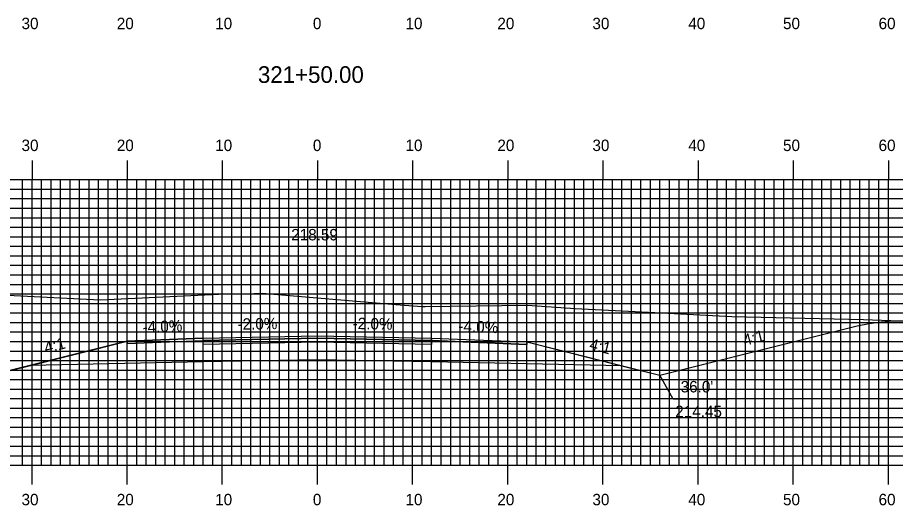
# Model space of a CAD drawing. Extents: x 1820424 to 1820768, y 442591 to 442811.
# Drawn here: x 1820558.7 to 1820650.9, y 442649.4 to 442700.7 of the extents above; entities that cross this region are included whole.
import ezdxf

# ---------------------------------------------------------------- set-up
doc = ezdxf.new("R2010")
doc.units = 0
for name, color, linetype in [('ANNOTATION', 7, 'Continuous'), ('D_Roadway_Centerline', 7, 'Continuous'), ('D_Roadway_Centerline_Text', 7, 'Continuous'), ('D_Roadway_Edge_Shoulder', 7, 'Continuous'), ('D_Roadway_Edge_TW', 7, 'Continuous'), ('D_Roadway_Pavement', 7, 'Continuous'), ('D_Roadway_SlopeLines', 7, 'Continuous'), ('D_Roadway_SubGrade', 7, 'Continuous'), ('H_V ANNOTATION', 7, 'Continuous'), ('MAJOR', 7, 'Continuous'), ('MINOR', 7, 'Continuous'), ('S_Roadway_Centerline', 7, 'Continuous')]:
    doc.layers.add(name, color=color, linetype=linetype)

msp = doc.modelspace()

# ---------------------------------------------------------------- linework, layer by layer
at = {"layer": 'ANNOTATION'}
msp.add_lwpolyline([(1820633.287, 442660.593), (1820627.596, 442660.593), (1820626.204, 442663.112)], dxfattribs=at)
at = {"layer": 'D_Roadway_Centerline'}
msp.add_lwpolyline([(1820513.438, 442673.203), (1820514.688, 442673.15), (1820515.938, 442673.023), (1820517.188, 442672.821), (1820518.438, 442672.546), (1820556.03, 442663.148), (1820560.03, 442664.148), (1820570.204, 442666.692), (1820578.204, 442667.012), (1820590.204, 442667.252), (1820602.204, 442667.012), (1820612.204, 442666.612), (1820622.204, 442664.112), (1820626.204, 442663.112), (1820646.944, 442668.297), (1820648.194, 442668.564), (1820649.444, 442668.742), (1820650.694, 442668.83), (1820651.944, 442668.828)], dxfattribs=at)
at = {"layer": 'D_Roadway_Edge_Shoulder'}
for points in [[(1820578.204, 442667.012), (1820570.204, 442666.692), (1820570.204, 442666.442), (1820578.204, 442666.762)], [(1820602.204, 442667.012), (1820612.204, 442666.612), (1820612.204, 442666.362), (1820602.204, 442666.762)]]:
    msp.add_lwpolyline(points, close=True, dxfattribs=at)
at = {"layer": 'D_Roadway_Edge_TW'}
msp.add_lwpolyline([(1820578.204, 442666.762), (1820578.204, 442667.012), (1820590.204, 442667.252), (1820602.204, 442667.012), (1820602.204, 442666.762), (1820590.204, 442667.002)], close=True, dxfattribs=at)
at = {"layer": 'D_Roadway_Pavement'}
msp.add_lwpolyline([(1820578.204, 442666.345), (1820578.204, 442666.762), (1820590.204, 442667.002), (1820602.204, 442666.762), (1820602.204, 442666.345), (1820590.204, 442666.585)], close=True, dxfattribs=at)
at = {"layer": 'D_Roadway_SlopeLines'}
for points in [[(1820626.204, 442663.112), (1820646.944, 442668.297), (1820648.194, 442668.564), (1820649.444, 442668.742), (1820650.694, 442668.83), (1820651.944, 442668.828)], [(1820570.204, 442666.692), (1820556.03, 442663.148)], [(1820612.204, 442666.612), (1820626.204, 442663.112)]]:
    msp.add_lwpolyline(points, dxfattribs=at)
at = {"layer": 'D_Roadway_SubGrade'}
msp.add_lwpolyline([(1820578.204, 442664.512), (1820560.03, 442664.148), (1820570.204, 442666.692), (1820570.204, 442666.442), (1820578.204, 442666.762), (1820590.204, 442667.002), (1820602.204, 442666.762), (1820612.204, 442666.362), (1820612.204, 442666.612), (1820622.204, 442664.112), (1820602.204, 442664.512), (1820590.204, 442664.752)], close=True, dxfattribs=at)
at = {"layer": 'MAJOR'}
for p, q in [((1820560.204, 442685.669), (1820560.204, 442683.665)), ((1820570.204, 442685.669), (1820570.204, 442683.665)), ((1820580.204, 442685.669), (1820580.204, 442683.665)), ((1820590.204, 442685.669), (1820590.204, 442683.665)), ((1820600.204, 442685.669), (1820600.204, 442683.665)), ((1820610.204, 442685.669), (1820610.204, 442683.665)), ((1820620.204, 442685.669), (1820620.204, 442683.665)), ((1820630.204, 442685.669), (1820630.204, 442683.665)), ((1820640.204, 442685.669), (1820640.204, 442683.665)), ((1820650.204, 442685.669), (1820650.204, 442683.665)), ((1820450.204, 442683.665), (1820730.204, 442683.665)), ((1820450.204, 442683.665), (1820730.204, 442683.665)), ((1820560.204, 442653.665), (1820560.204, 442683.665)), ((1820570.204, 442653.665), (1820570.204, 442683.665)), ((1820580.204, 442653.665), (1820580.204, 442683.665)), ((1820590.204, 442653.665), (1820590.204, 442683.665)), ((1820600.204, 442653.665), (1820600.204, 442683.665)), ((1820610.204, 442653.665), (1820610.204, 442683.665)), ((1820620.204, 442653.665), (1820620.204, 442683.665)), ((1820630.204, 442653.665), (1820630.204, 442683.665)), ((1820640.204, 442653.665), (1820640.204, 442683.665)), ((1820650.204, 442653.665), (1820650.204, 442683.665)), ((1820450.204, 442678.665), (1820730.204, 442678.665)), ((1820450.204, 442673.665), (1820730.204, 442673.665)), ((1820450.204, 442668.665), (1820730.204, 442668.665)), ((1820450.204, 442663.665), (1820730.204, 442663.665)), ((1820450.204, 442658.665), (1820730.204, 442658.665)), ((1820450.204, 442653.665), (1820730.204, 442653.665)), ((1820450.204, 442653.665), (1820730.204, 442653.665)), ((1820560.204, 442651.661), (1820560.204, 442653.665)), ((1820570.204, 442651.661), (1820570.204, 442653.665)), ((1820580.204, 442651.661), (1820580.204, 442653.665)), ((1820590.204, 442651.661), (1820590.204, 442653.665)), ((1820600.204, 442651.661), (1820600.204, 442653.665)), ((1820610.204, 442651.661), (1820610.204, 442653.665)), ((1820620.204, 442651.661), (1820620.204, 442653.665)), ((1820630.204, 442651.661), (1820630.204, 442653.665)), ((1820640.204, 442651.661), (1820640.204, 442653.665)), ((1820650.204, 442651.661), (1820650.204, 442653.665))]:
    msp.add_line(p, q, dxfattribs=at)
at = {"layer": 'MINOR'}
for p, q in [((1820559.204, 442653.665), (1820559.204, 442683.665)), ((1820561.204, 442653.665), (1820561.204, 442683.665)), ((1820562.204, 442653.665), (1820562.204, 442683.665)), ((1820563.204, 442653.665), (1820563.204, 442683.665)), ((1820564.204, 442653.665), (1820564.204, 442683.665)), ((1820565.204, 442653.665), (1820565.204, 442683.665)), ((1820566.204, 442653.665), (1820566.204, 442683.665)), ((1820567.204, 442653.665), (1820567.204, 442683.665)), ((1820568.204, 442653.665), (1820568.204, 442683.665)), ((1820569.204, 442653.665), (1820569.204, 442683.665)), ((1820571.204, 442653.665), (1820571.204, 442683.665)), ((1820572.204, 442653.665), (1820572.204, 442683.665)), ((1820573.204, 442653.665), (1820573.204, 442683.665)), ((1820574.204, 442653.665), (1820574.204, 442683.665)), ((1820575.204, 442653.665), (1820575.204, 442683.665)), ((1820576.204, 442653.665), (1820576.204, 442683.665)), ((1820577.204, 442653.665), (1820577.204, 442683.665)), ((1820578.204, 442653.665), (1820578.204, 442683.665)), ((1820579.204, 442653.665), (1820579.204, 442683.665)), ((1820581.204, 442653.665), (1820581.204, 442683.665)), ((1820582.204, 442653.665), (1820582.204, 442683.665)), ((1820583.204, 442653.665), (1820583.204, 442683.665)), ((1820584.204, 442653.665), (1820584.204, 442683.665)), ((1820585.204, 442653.665), (1820585.204, 442683.665)), ((1820586.204, 442653.665), (1820586.204, 442683.665)), ((1820587.204, 442653.665), (1820587.204, 442683.665)), ((1820588.204, 442653.665), (1820588.204, 442683.665)), ((1820589.204, 442653.665), (1820589.204, 442683.665)), ((1820591.204, 442653.665), (1820591.204, 442683.665)), ((1820592.204, 442653.665), (1820592.204, 442683.665)), ((1820593.204, 442653.665), (1820593.204, 442683.665)), ((1820594.204, 442653.665), (1820594.204, 442683.665)), ((1820595.204, 442653.665), (1820595.204, 442683.665)), ((1820596.204, 442653.665), (1820596.204, 442683.665)), ((1820597.204, 442653.665), (1820597.204, 442683.665)), ((1820598.204, 442653.665), (1820598.204, 442683.665)), ((1820599.204, 442653.665), (1820599.204, 442683.665)), ((1820601.204, 442653.665), (1820601.204, 442683.665)), ((1820602.204, 442653.665), (1820602.204, 442683.665)), ((1820603.204, 442653.665), (1820603.204, 442683.665)), ((1820604.204, 442653.665), (1820604.204, 442683.665)), ((1820605.204, 442653.665), (1820605.204, 442683.665)), ((1820606.204, 442653.665), (1820606.204, 442683.665)), ((1820607.204, 442653.665), (1820607.204, 442683.665)), ((1820608.204, 442653.665), (1820608.204, 442683.665)), ((1820609.204, 442653.665), (1820609.204, 442683.665)), ((1820611.204, 442653.665), (1820611.204, 442683.665)), ((1820612.204, 442653.665), (1820612.204, 442683.665)), ((1820613.204, 442653.665), (1820613.204, 442683.665)), ((1820614.204, 442653.665), (1820614.204, 442683.665)), ((1820615.204, 442653.665), (1820615.204, 442683.665)), ((1820616.204, 442653.665), (1820616.204, 442683.665)), ((1820617.204, 442653.665), (1820617.204, 442683.665)), ((1820618.204, 442653.665), (1820618.204, 442683.665)), ((1820619.204, 442653.665), (1820619.204, 442683.665)), ((1820621.204, 442653.665), (1820621.204, 442683.665)), ((1820622.204, 442653.665), (1820622.204, 442683.665)), ((1820623.204, 442653.665), (1820623.204, 442683.665)), ((1820624.204, 442653.665), (1820624.204, 442683.665)), ((1820625.204, 442653.665), (1820625.204, 442683.665)), ((1820626.204, 442653.665), (1820626.204, 442683.665)), ((1820627.204, 442653.665), (1820627.204, 442683.665)), ((1820628.204, 442653.665), (1820628.204, 442683.665)), ((1820629.204, 442653.665), (1820629.204, 442683.665)), ((1820631.204, 442653.665), (1820631.204, 442683.665)), ((1820632.204, 442653.665), (1820632.204, 442683.665)), ((1820633.204, 442653.665), (1820633.204, 442683.665)), ((1820634.204, 442653.665), (1820634.204, 442683.665)), ((1820635.204, 442653.665), (1820635.204, 442683.665)), ((1820636.204, 442653.665), (1820636.204, 442683.665)), ((1820637.204, 442653.665), (1820637.204, 442683.665)), ((1820638.204, 442653.665), (1820638.204, 442683.665)), ((1820639.204, 442653.665), (1820639.204, 442683.665)), ((1820641.204, 442653.665), (1820641.204, 442683.665)), ((1820642.204, 442653.665), (1820642.204, 442683.665)), ((1820643.204, 442653.665), (1820643.204, 442683.665)), ((1820644.204, 442653.665), (1820644.204, 442683.665)), ((1820645.204, 442653.665), (1820645.204, 442683.665)), ((1820646.204, 442653.665), (1820646.204, 442683.665)), ((1820647.204, 442653.665), (1820647.204, 442683.665)), ((1820648.204, 442653.665), (1820648.204, 442683.665)), ((1820649.204, 442653.665), (1820649.204, 442683.665)), ((1820450.204, 442682.665), (1820730.204, 442682.665)), ((1820450.204, 442681.665), (1820730.204, 442681.665)), ((1820450.204, 442680.665), (1820730.204, 442680.665)), ((1820450.204, 442679.665), (1820730.204, 442679.665)), ((1820450.204, 442677.665), (1820730.204, 442677.665)), ((1820450.204, 442676.665), (1820730.204, 442676.665)), ((1820450.204, 442675.665), (1820730.204, 442675.665)), ((1820450.204, 442674.665), (1820730.204, 442674.665)), ((1820450.204, 442672.665), (1820730.204, 442672.665)), ((1820450.204, 442671.665), (1820730.204, 442671.665)), ((1820450.204, 442670.665), (1820730.204, 442670.665)), ((1820450.204, 442669.665), (1820730.204, 442669.665)), ((1820450.204, 442667.665), (1820730.204, 442667.665)), ((1820450.204, 442666.665), (1820730.204, 442666.665)), ((1820450.204, 442665.665), (1820730.204, 442665.665)), ((1820450.204, 442664.665), (1820730.204, 442664.665)), ((1820450.204, 442662.665), (1820730.204, 442662.665)), ((1820450.204, 442661.665), (1820730.204, 442661.665)), ((1820450.204, 442660.665), (1820730.204, 442660.665)), ((1820450.204, 442659.665), (1820730.204, 442659.665)), ((1820450.204, 442657.665), (1820730.204, 442657.665)), ((1820450.204, 442656.665), (1820730.204, 442656.665)), ((1820450.204, 442655.665), (1820730.204, 442655.665)), ((1820450.204, 442654.665), (1820730.204, 442654.665))]:
    msp.add_line(p, q, dxfattribs=at)
at = {"layer": 'S_Roadway_Centerline'}
msp.add_lwpolyline([(1820498.303, 442672.852), (1820511.912, 442673.223), (1820516.459, 442673.164), (1820527.785, 442672.737), (1820532.579, 442672.401), (1820534.444, 442672.395), (1820550.151, 442671.846), (1820558.334, 442671.488), (1820567.357, 442671.055), (1820579.852, 442671.621), (1820582.622, 442671.68), (1820584.383, 442671.723), (1820598.427, 442670.566), (1820601.19, 442670.339), (1820601.511, 442670.338), (1820612.268, 442670.478), (1820617.289, 442670.123), (1820624.983, 442669.743), (1820633.743, 442669.299), (1820647.596, 442668.99), (1820651.414, 442668.849)], dxfattribs=at)

# ---------------------------------------------------------------- texts
at = {"layer": 'ANNOTATION'}
for s, rotation, p in [('-4.0%', 2.29061, (1820571.836, 442667.559)), ('-2.0%', 1.14576, (1820581.81, 442667.884)), ('-2.0%', 358.85424, (1820593.89, 442667.978)), ('-4.0%', 357.70939, (1820604.996, 442667.702)), ('4:1', 14.03624, (1820635.11, 442666.2)), ('4:1', 14.03624, (1820561.652, 442665.415)), ('4:1', 345.96376, (1820618.71, 442665.847))]:
    msp.add_text(s, height=1.2, rotation=rotation, dxfattribs=at).set_placement(p)
for s, p in [("36.0'", (1820628.373, 442661.319)), ('214.45', (1820627.806, 442658.719))]:
    msp.add_text(s, height=1.2, dxfattribs=at).set_placement(p)
at = {"layer": 'D_Roadway_Centerline'}
for s, p in [('C', (1820590.199, 442667.252)), ('L', (1820590.204, 442667.244))]:
    msp.add_text(s, height=0.0146, dxfattribs=at).set_placement(p)
at = {"layer": 'D_Roadway_Centerline_Text'}
msp.add_text('218.59', height=1.2, dxfattribs=at).set_placement((1820587.443, 442677.282))
at = {"layer": 'H_V ANNOTATION'}
for s, height, p in [('30', 1.2, (1820559.101, 442699.465)), ('20', 1.2, (1820569.112, 442699.465)), ('10', 1.2, (1820579.455, 442699.465)), ('0', 1.2, (1820589.722, 442699.465)), ('10', 1.2, (1820599.455, 442699.465)), ('20', 1.2, (1820609.112, 442699.465)), ('30', 1.2, (1820619.101, 442699.465)), ('40', 1.2, (1820629.176, 442699.465)), ('50', 1.2, (1820639.133, 442699.465)), ('60', 1.2, (1820649.176, 442699.465)), ('321+50.00', 1.75, (1820583.946, 442693.821)), ('30', 1.2, (1820559.101, 442686.665)), ('20', 1.2, (1820569.112, 442686.665)), ('10', 1.2, (1820579.455, 442686.665)), ('0', 1.2, (1820589.722, 442686.665)), ('10', 1.2, (1820599.455, 442686.665)), ('20', 1.2, (1820609.112, 442686.665)), ('30', 1.2, (1820619.101, 442686.665)), ('40', 1.2, (1820629.176, 442686.665)), ('50', 1.2, (1820639.133, 442686.665)), ('60', 1.2, (1820649.176, 442686.665)), ('30', 1.2, (1820559.101, 442649.465)), ('20', 1.2, (1820569.112, 442649.465)), ('10', 1.2, (1820579.455, 442649.465)), ('0', 1.2, (1820589.722, 442649.465)), ('10', 1.2, (1820599.455, 442649.465)), ('20', 1.2, (1820609.112, 442649.465)), ('30', 1.2, (1820619.101, 442649.465)), ('40', 1.2, (1820629.176, 442649.465)), ('50', 1.2, (1820639.133, 442649.465)), ('60', 1.2, (1820649.176, 442649.465))]:
    msp.add_text(s, height=height, dxfattribs=at).set_placement(p)

doc.saveas('drawing.dxf')
